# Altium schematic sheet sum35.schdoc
size 594 x 419 mm; Symbol: Drawing-Symbol_A4; @Project Name: Inverted_MAML_6x6; @Page Count: 1; @Update Date: 2026-06-14; @Create Date: 2026-06-14; @Schematic Name: Schematic1; @Page No: 1; @Page Name: P1; Company: EasyEDA.com; Version: V1.0; Page Size: A4; Drawn: Olle Welin; Device: Drawing-Symbol_A4; @Create Time: 14:27:06; @Update Time: 14:27:06; Border: 1; Width: 2338; Height: 1652; Region Start: 1; X Region Count: 6; Y Region Count: 4; Blade Width: 10; Title Block Position: 3
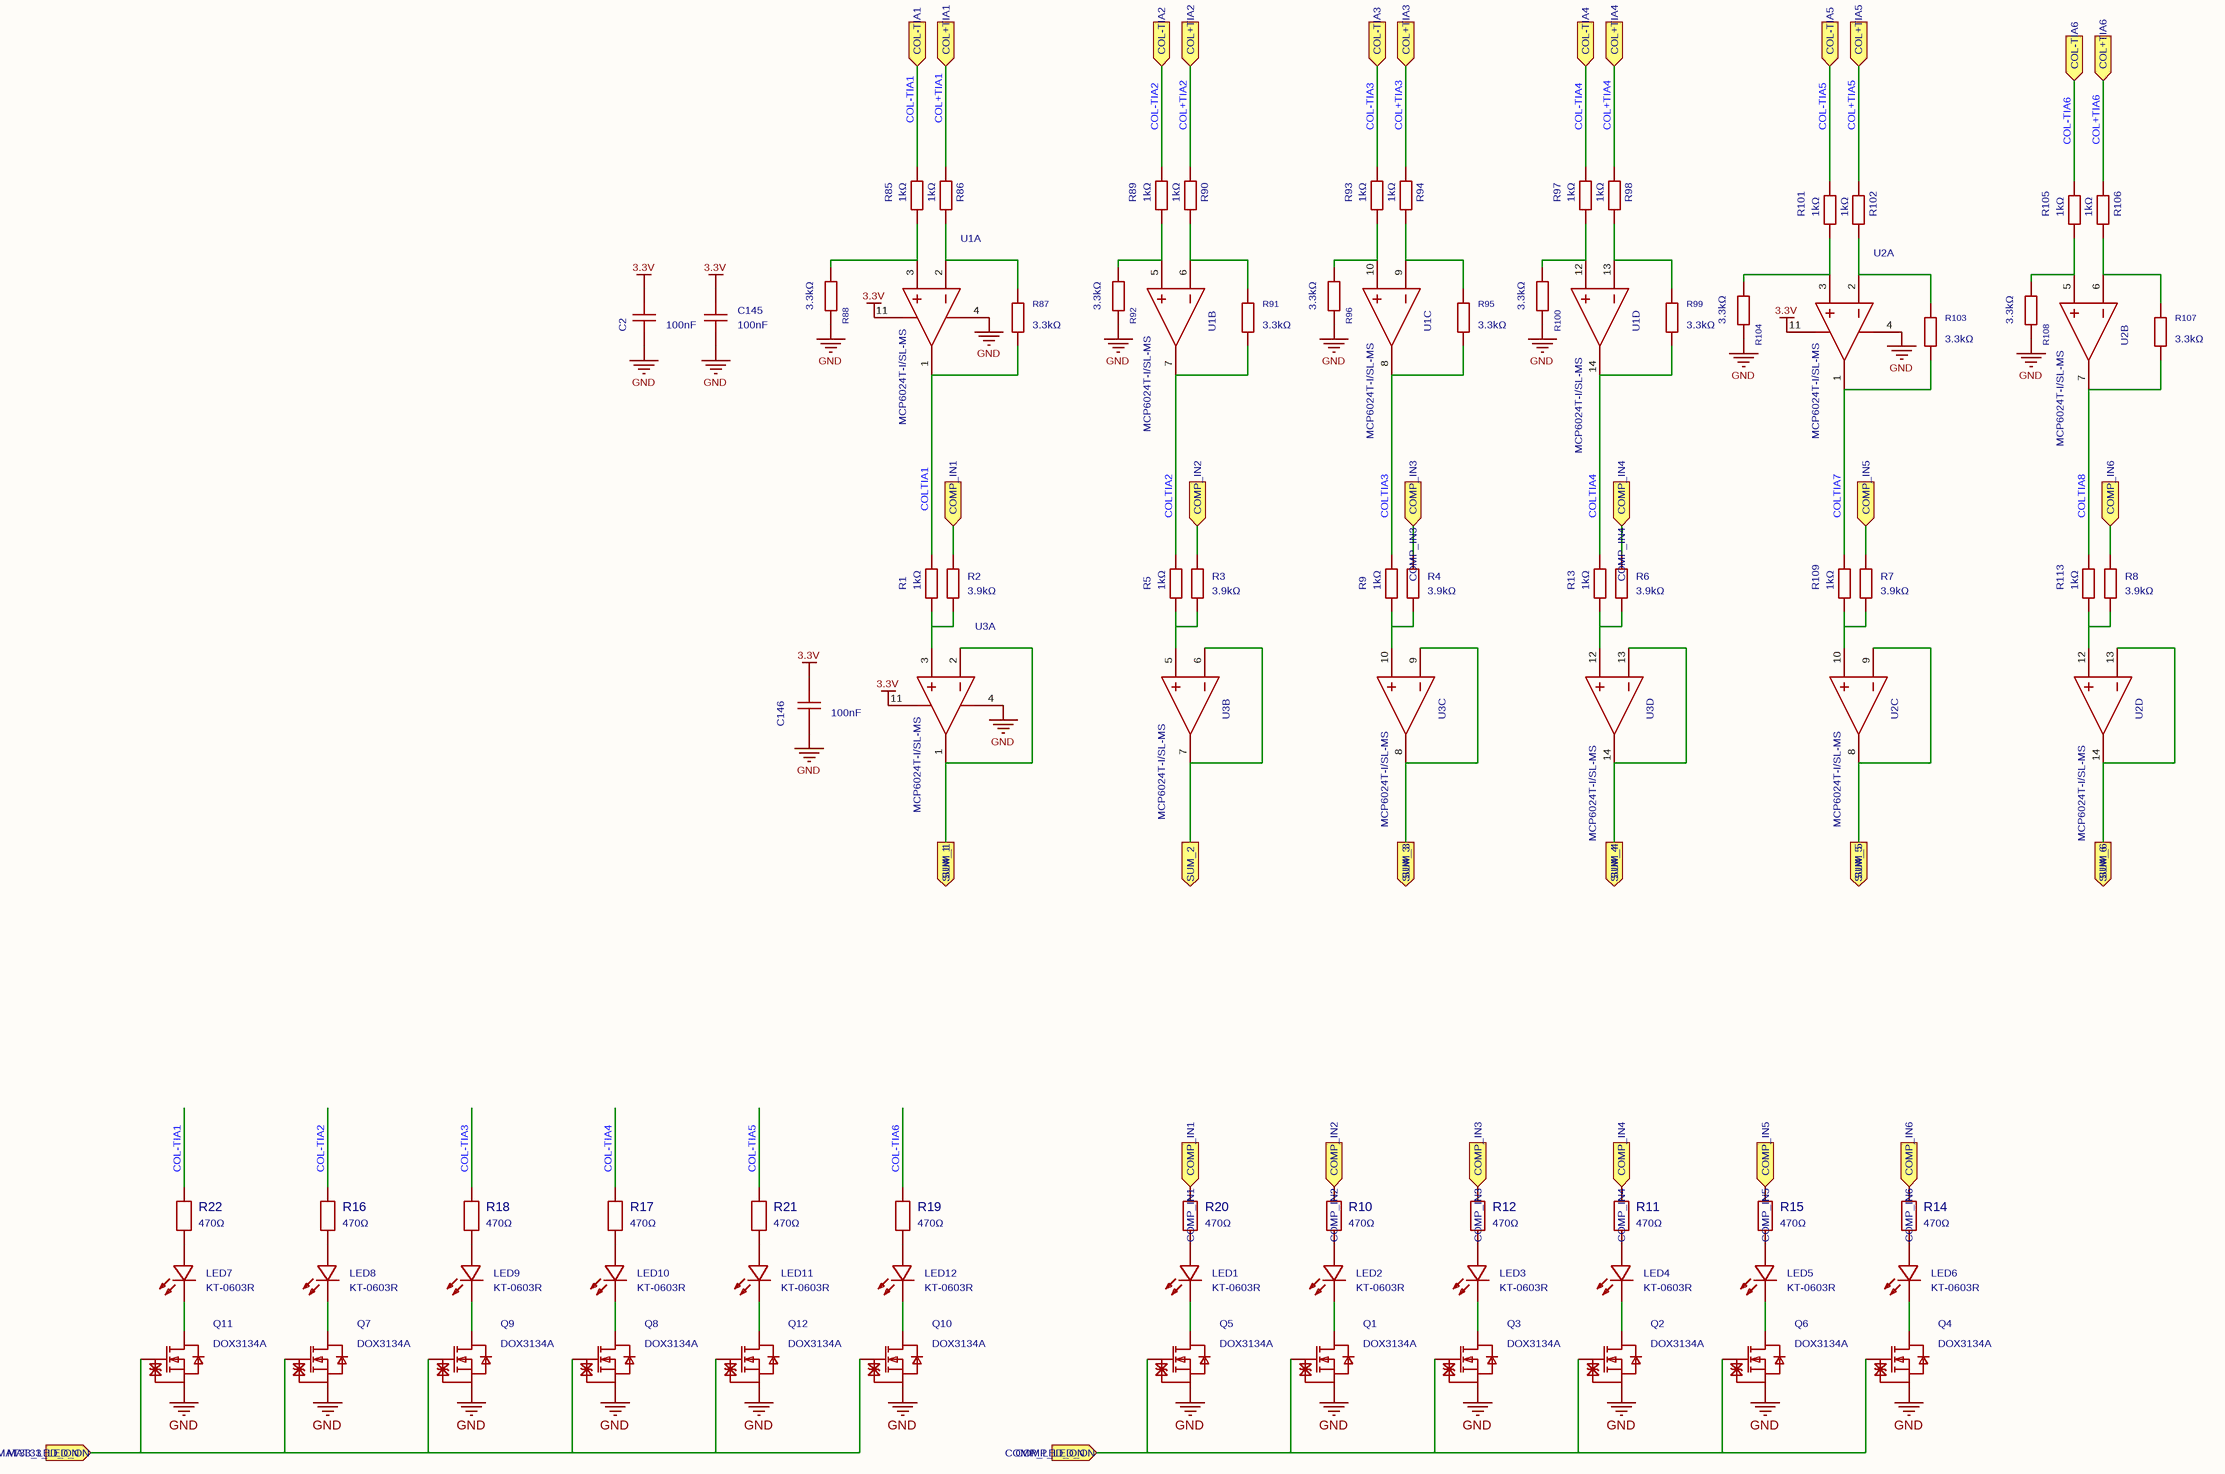
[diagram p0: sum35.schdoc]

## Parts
C2  100nF  [C0402]
C145  100nF  [C0402]
C146  100nF  [C0402]
LED1  KT-0603R  [LED0603-RD]
LED2  KT-0603R  [LED0603-RD]
LED3  KT-0603R  [LED0603-RD]
LED4  KT-0603R  [LED0603-RD]
LED5  KT-0603R  [LED0603-RD]
LED6  KT-0603R  [LED0603-RD]
LED7  KT-0603R  [LED0603-RD]
LED8  KT-0603R  [LED0603-RD]
LED9  KT-0603R  [LED0603-RD]
LED10  KT-0603R  [LED0603-RD]
LED11  KT-0603R  [LED0603-RD]
LED12  KT-0603R  [LED0603-RD]
Q1  DOX3134A  [SOT-323-3_L2.1-W1.3-P1.30-LS2.3-BR]
Q2  DOX3134A  [SOT-323-3_L2.1-W1.3-P1.30-LS2.3-BR]
Q3  DOX3134A  [SOT-323-3_L2.1-W1.3-P1.30-LS2.3-BR]
Q4  DOX3134A  [SOT-323-3_L2.1-W1.3-P1.30-LS2.3-BR]
Q5  DOX3134A  [SOT-323-3_L2.1-W1.3-P1.30-LS2.3-BR]
Q6  DOX3134A  [SOT-323-3_L2.1-W1.3-P1.30-LS2.3-BR]
Q7  DOX3134A  [SOT-323-3_L2.1-W1.3-P1.30-LS2.3-BR]
Q8  DOX3134A  [SOT-323-3_L2.1-W1.3-P1.30-LS2.3-BR]
Q9  DOX3134A  [SOT-323-3_L2.1-W1.3-P1.30-LS2.3-BR]
Q10  DOX3134A  [SOT-323-3_L2.1-W1.3-P1.30-LS2.3-BR]
Q11  DOX3134A  [SOT-323-3_L2.1-W1.3-P1.30-LS2.3-BR]
Q12  DOX3134A  [SOT-323-3_L2.1-W1.3-P1.30-LS2.3-BR]
R1  1kΩ  [R0402]
R2  3.9kΩ  [R0402]
R3  3.9kΩ  [R0402]
R4  3.9kΩ  [R0402]
R5  1kΩ  [R0402]
R6  3.9kΩ  [R0402]
R7  3.9kΩ  [R0402]
R8  3.9kΩ  [R0402]
R9  1kΩ  [R0402]
R10  470Ω  [R0402]
R11  470Ω  [R0402]
R12  470Ω  [R0402]
R13  1kΩ  [R0402]
R14  470Ω  [R0402]
R15  470Ω  [R0402]
R16  470Ω  [R0402]
R17  470Ω  [R0402]
R18  470Ω  [R0402]
R19  470Ω  [R0402]
R20  470Ω  [R0402]
R21  470Ω  [R0402]
R22  470Ω  [R0402]
R85  1kΩ  [R0402]
R86  1kΩ  [R0402]
R87  3.3kΩ  [R0402]
R88  3.3kΩ  [R0402]
R89  1kΩ  [R0402]
R90  1kΩ  [R0402]
R91  3.3kΩ  [R0402]
R92  3.3kΩ  [R0402]
R93  1kΩ  [R0402]
R94  1kΩ  [R0402]
R95  3.3kΩ  [R0402]
R96  3.3kΩ  [R0402]
R97  1kΩ  [R0402]
R98  1kΩ  [R0402]
R99  3.3kΩ  [R0402]
R100  3.3kΩ  [R0402]
R101  1kΩ  [R0402]
R102  1kΩ  [R0402]
R103  3.3kΩ  [R0402]
R104  3.3kΩ  [R0402]
R105  1kΩ  [R0402]
R106  1kΩ  [R0402]
R107  3.3kΩ  [R0402]
R108  3.3kΩ  [R0402]
R109  1kΩ  [R0402]
R113  1kΩ  [R0402]
U1  MCP6024T-I/SL-MS  [SOIC-14_L8.7-W3.9-P1.27-LS6.0-BL-1]  (parts A,B,C,D of 4)
U2  MCP6024T-I/SL-MS  [SOIC-14_L8.7-W3.9-P1.27-LS6.0-BL-1]  (parts A,B,C,D of 4)
U3  MCP6024T-I/SL-MS  [SOIC-14_L8.7-W3.9-P1.27-LS6.0-BL-1]  (parts A,B,C,D of 4)

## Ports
COL+TIA1 (in), COL+TIA2 (in), COL+TIA3 (in), COL+TIA4 (in), COL+TIA5 (in), COL+TIA6 (in), COL-TIA1 (in), COL-TIA2 (in), COL-TIA3 (in), COL-TIA4 (in), COL-TIA5 (in), COL-TIA6 (in), COMP_IN1 (in), COMP_IN2 (in), COMP_IN3 (in), COMP_IN4 (in), COMP_IN5 (in), COMP_IN6 (in), COMP_LED_ON (in), MAT33_LED_ON (in), SUM_1 (out), SUM_2 (out), SUM_3 (out), SUM_4 (out), SUM_5 (out), SUM_6 (out)

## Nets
3.3V: C2.2 C145.2 C146.2 U1.11(V-) U2.11(V-) U3.11(V-)
GND: C2.1 C145.1 C146.1 Q1.2(S) Q2.2(S) Q3.2(S) Q4.2(S) Q5.2(S) Q6.2(S) Q7.2(S) Q8.2(S) Q9.2(S) Q10.2(S) Q11.2(S) Q12.2(S) R88.1 R92.1 R96.1 R100.1 R104.1 R108.1 U1.4(V+) U2.4(V+) U3.4(V+)
COL+TIA1: R86.2 ; port COL+TIA1
COL+TIA2: R90.2 ; port COL+TIA2
COL+TIA3: R94.2 ; port COL+TIA3
COL+TIA4: R98.2 ; port COL+TIA4
COL+TIA5: R102.2 ; port COL+TIA5
COL+TIA6: R106.2 ; port COL+TIA6
COL-TIA1: R22.2 R85.2 ; port COL-TIA1
COL-TIA2: R16.2 R89.2 ; port COL-TIA2
COL-TIA3: R18.2 R93.2 ; port COL-TIA3
COL-TIA4: R17.2 R97.2 ; port COL-TIA4
COL-TIA5: R21.2 R101.2 ; port COL-TIA5
COL-TIA6: R19.2 R105.2 ; port COL-TIA6
COLTIA1: R1.2 R87.1 U1.1(OUT1)
COLTIA2: R5.2 R91.1 U1.7(OUT2)
COLTIA3: R9.2 R95.1 U1.8(OUT3)
COLTIA4: R13.2 R99.1 U1.14(OUT4)
COLTIA7: R103.1 R109.2 U2.1(OUT1)
COLTIA8: R107.1 R113.2 U2.7(OUT2)
COMP_IN1: R2.2 R20.2 ; port COMP_IN1
COMP_IN2: R3.2 R10.2 ; port COMP_IN2
COMP_IN3: R4.2 R12.2 ; port COMP_IN3
COMP_IN4: R6.2 R11.2 ; port COMP_IN4
COMP_IN5: R7.2 R15.2 ; port COMP_IN5
COMP_IN6: R8.2 R14.2 ; port COMP_IN6
COMP_LED_ON: Q1.1(G) Q2.1(G) Q3.1(G) Q4.1(G) Q5.1(G) Q6.1(G) ; port COMP_LED_ON
MAT33_LED_ON: Q7.1(G) Q8.1(G) Q9.1(G) Q10.1(G) Q11.1(G) Q12.1(G) ; port MAT33_LED_ON
SUM_1: U3.1(OUT1) U3.2(IN1-) ; port SUM_1
SUM_2: U3.6(IN2-) U3.7(OUT2) ; port SUM_2
SUM_3: U3.8(OUT3) U3.9(IN3-) ; port SUM_3
SUM_4: U3.13(IN4-) U3.14(OUT4) ; port SUM_4
SUM_5: U2.8(OUT3) U2.9(IN3-) ; port SUM_5
SUM_6: U2.13(IN4-) U2.14(OUT4) ; port SUM_6
NetLED1_1: LED1.1(K) Q5.3(D)
NetLED1_2: LED1.2(A) R20.1
NetLED2_1: LED2.1(K) Q1.3(D)
NetLED2_2: LED2.2(A) R10.1
NetLED3_1: LED3.1(K) Q3.3(D)
NetLED3_2: LED3.2(A) R12.1
NetLED4_1: LED4.1(K) Q2.3(D)
NetLED4_2: LED4.2(A) R11.1
NetLED5_1: LED5.1(K) Q6.3(D)
NetLED5_2: LED5.2(A) R15.1
NetLED6_1: LED6.1(K) Q4.3(D)
NetLED6_2: LED6.2(A) R14.1
NetLED7_1: LED7.1(K) Q11.3(D)
NetLED7_2: LED7.2(A) R22.1
NetLED8_1: LED8.1(K) Q7.3(D)
NetLED8_2: LED8.2(A) R16.1
NetLED9_1: LED9.1(K) Q9.3(D)
NetLED9_2: LED9.2(A) R18.1
NetLED10_1: LED10.1(K) Q8.3(D)
NetLED10_2: LED10.2(A) R17.1
NetLED11_1: LED11.1(K) Q12.3(D)
NetLED11_2: LED11.2(A) R21.1
NetLED12_1: LED12.1(K) Q10.3(D)
NetLED12_2: LED12.2(A) R19.1
NetR1_1: R1.1 R2.1 U3.3(IN1+)
NetR3_1: R3.1 R5.1 U3.5(IN2+)
NetR4_1: R4.1 R9.1 U3.10(IN3+)
NetR6_1: R6.1 R13.1 U3.12(IN4+)
NetR7_1: R7.1 R109.1 U2.10(IN3+)
NetR8_1: R8.1 R113.1 U2.12(IN4+)
NetR85_1: R85.1 R88.2 U1.3(IN1+)
NetR86_1: R86.1 R87.2 U1.2(IN1-)
NetR89_1: R89.1 R92.2 U1.5(IN2+)
NetR90_1: R90.1 R91.2 U1.6(IN2-)
NetR93_1: R93.1 R96.2 U1.10(IN3+)
NetR94_1: R94.1 R95.2 U1.9(IN3-)
NetR97_1: R97.1 R100.2 U1.12(IN4+)
NetR98_1: R98.1 R99.2 U1.13(IN4-)
NetR101_1: R101.1 R104.2 U2.3(IN1+)
NetR102_1: R102.1 R103.2 U2.2(IN1-)
NetR105_1: R105.1 R108.2 U2.5(IN2+)
NetR106_1: R106.1 R107.2 U2.6(IN2-)

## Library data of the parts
C2 C145 C146 = CL05B104KO5NNNC: Capacitance:100nF Tolerance:±10% Tolerance:±10% Voltage Rating:16V Temperature Coefficient:X7R; Manufacturer: SAMSUNG(三星); 3D Model: b7d13df3e9464d7a99d0651d1a5b4d570819f05c4eef4c71ace90d822a990e87; 3D Model Transform: 39.37,19.685,0,0,0,0,0,0,0; Tolerance: ±10%; Voltage Rating: 16V; Temperature Coefficient: X7R; AddInBom: yes; ModelName: C0402_L1.0-W0.5-H0.5
LED1-LED12 = KT-0603R: Emitted Color:Red Power Dissipation:- Forward Current:- Dominant Wavelength:- Dominant Wavelength:- Peak Wavelength:- Diode Configuration:- Lens Color:- Color Temperature:- Color Temperature:- Viewing Angle:- Mounting Sytle:- Operating Temperature:-40℃~+8; Manufacturer: KENTO; 3D Model: 5e3b568068dd46cf8019c1d1baa0031b; 3D Model Transform: 63.7794,32.283,0,0,0,0,0,0,0; Emitted Color: Red; AddInBom: yes
Q1-Q12 = DOX3134A: Number:1 N-channel Drain to Source Voltage:20V Current - Continuous Drain(Id):900mA RDS(on):120Ω@4.5V Pd - Power Dissipation:220mW Gate Threshold Voltage (Vgs(th)):600mV Gate Charge(Qg):1nC@4.5V Input Capacitance(Ciss):63pF Reverse Transfer Capacitance (C; Manufacturer: DOINGTER(杜因特); 3D Model: 4ef9dcfb8d16439f88dacdf9bd184e54; 3D Model Transform: 90.551,78.74,0,0,0,0,0,0,0; Drain to Source Voltage: 20V; Current - Continuous Drain(Id): 900mA; Pd - Power Dissipation: 220mW; Gate Threshold Voltage (Vgs(th)): 600mV; Input Capacitance(Ciss): 63pF; Reverse Transfer Capacitance (Crss@Vds): 12pF; Output Capacitance(Coss): 23pF; AddInBom: yes
R1 R5 R9 R13 R85 R86 R89 R90 R93 R94 R97 R98 R101 R102 R105 R106 R109 R113 = 0402WGF1001TCE: Type:Thick Film Resistor Resistance:1kΩ Tolerance:±1% Tolerance:±1% Power(Watts):62.5mW Voltage-Supply(Max):50V Temperature Coefficient:±100ppm/℃ Temperature Coefficient:±100ppm/℃ Operating Temperature:-55℃~+155℃ Operating Temperature:-55℃~+155℃; Manufacturer: UNI-ROYAL(厚声); 3D Model: efdecb7dae4442949d28eecaf748420f0819f05c4eef4c71ace90d822a990e87; 3D Model Transform: 39.37,19.685,0,0,0,0,0,0,0; Tolerance: ±1%; Power(Watts): 62.5mW; Voltage-Supply(Max): 50V; AddInBom: yes; ModelName: R0402_L1.0-W0.5-H0.4
R2-R4 R6-R8 = 0402WGF3901TCE: Type:Thick Film Resistor Resistance:3.9kΩ Tolerance:±1% Tolerance:±1% Power(Watts):62.5mW Voltage-Supply(Max):50V Temperature Coefficient:±100ppm/℃ Temperature Coefficient:±100ppm/℃ Operating Temperature:-55℃~+155℃ Operating Temperature:-55℃~+155℃; Manufacturer: UNI-ROYAL(厚声); AddInBom: yes; ModelId: efdecb7dae4442949d28eecaf748420f0819f05c4eef4c71ace90d822a990e87; ModelName: R0402_L1.0-W0.5-H0.4; ModelTransform: 39.37,19.685,0,0,0,0,0,0,0; Tolerance: ±1%; Power(Watts): 62.5mW; Voltage-Supply(Max): 50V
R10-R12 R14-R22 = 0402WGF4700TCE: Type:Thick Film Resistors Resistance: Tolerance:±1% Tolerance:±1% Power(Watts): Overload Voltage (Max): Temperature Coefficient:±100ppm/℃ Temperature Coefficient:±100ppm/℃ Operating Temperature Range:-55℃~+155℃ Operating Temperature Range:-55℃~+155℃; Manufacturer: UNI-ROYAL(厚声); Symbol: ERJ2RKF4700X; 3D Model: efdecb7dae4442949d28eecaf748420f; 3D Model Transform: 39.37,19.685,0,0,0,0,0,0,0; Tolerance: ±1%; AddInBom: yes; ModelName: R0402_L1.0-W0.5-H0.4
R87 R88 R91 R92 R95 R96 R99 R100 R103 R104 R107 R108 = 0402WGF3301TCE: Type:Thick Film Resistor Resistance:3.3kΩ Tolerance:±1% Tolerance:±1% Power(Watts):62.5mW Voltage-Supply(Max):50V Temperature Coefficient:±100ppm/℃ Temperature Coefficient:±100ppm/℃ Operating Temperature:-55℃~+155℃ Operating Temperature:-55℃~+155℃; Manufacturer: UNI-ROYAL(厚声); 3D Model: efdecb7dae4442949d28eecaf748420f0819f05c4eef4c71ace90d822a990e87; 3D Model Transform: 39.37,19.685,0,0,0,0,0,0,0; Tolerance: ±1%; Power(Watts): 62.5mW; Voltage-Supply(Max): 50V; AddInBom: yes; ModelName: R0402_L1.0-W0.5-H0.4
U1-U3 = MCP6024T-I/SL-MS: Manufacturer: MSKSEMI(美森科); Relevance: []; AddInBom: yes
